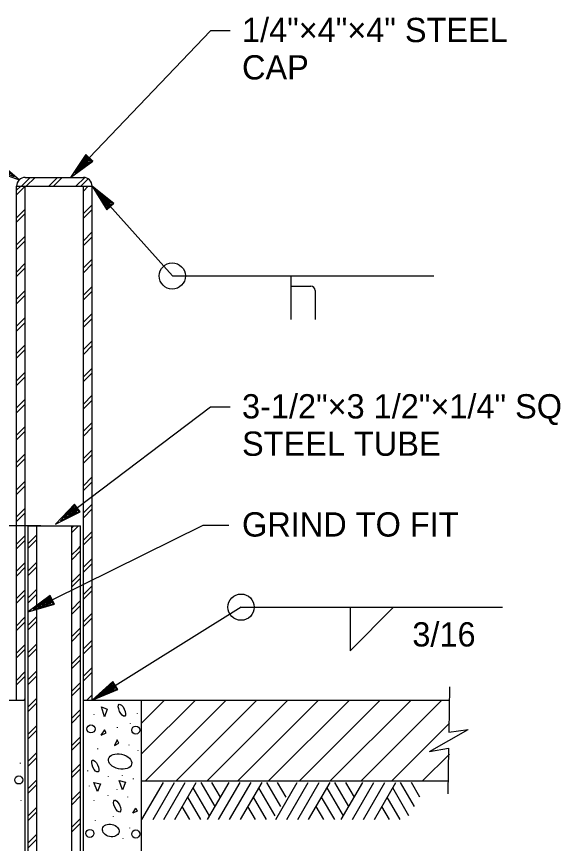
# Model space of a CAD drawing. Extents: x -119017 to -116080, y -104449 to -102845.
# Drawn here: x -117755.4 to -117621.1, y -103410.1 to -103205.8 of the extents above; entities that cross this region are included whole.
import ezdxf

# ---------------------------------------------------------------- set-up
doc = ezdxf.new("R2010")
doc.units = 0
for name, color, linetype in [('C-DETL-MEDM', 7, 'Continuous'), ('C-DIMS', 7, 'Continuous'), ('C-MARK', 7, 'Continuous'), ('C-PATT', 7, 'Continuous'), ('C-TEXT', 7, 'Continuous'), ('Misc CnstDet(22)', 7, 'Continuous')]:
    doc.layers.add(name, color=color, linetype=linetype)

msp = doc.modelspace()

# ---------------------------------------------------------------- linework, layer by layer
at = {"layer": 'C-DETL-MEDM'}
for p, q in [((-117753.26, -103245.52), (-117738.92, -103245.52)), ((-117755.42, -103247.67), (-117736.76, -103247.67)), ((-117755.42, -103374.64), (-117755.42, -103247.67)), ((-117753.26, -103374.64), (-117753.26, -103247.67)), ((-117738.92, -103374.64), (-117738.92, -103247.67)), ((-117736.76, -103374.64), (-117736.76, -103247.67)), ((-117752.59, -103482.24), (-117752.59, -103331.6)), ((-117752.59, -103331.6), (-117739.59, -103331.6)), ((-117750.44, -103482.2), (-117750.44, -103331.6)), ((-117741.74, -103482.2), (-117741.74, -103331.6)), ((-117739.59, -103482.24), (-117739.59, -103331.6)), ((-117828.02, -103374.64), (-117753.26, -103374.64)), ((-117753.26, -103503.76), (-117753.26, -103374.64)), ((-117738.92, -103503.76), (-117738.92, -103374.64)), ((-117738.92, -103374.64), (-117648.54, -103374.64)), ((-117724.57, -103503.76), (-117724.57, -103374.64)), ((-117724.57, -103394.59), (-117648.86, -103394.59))]:
    msp.add_line(p, q, dxfattribs=at)
for centre, start, end in [((-117753.26, -103247.67), 90, 180), ((-117738.92, -103247.67), 0, 90)]:
    msp.add_arc(centre, 2.15, start, end, dxfattribs=at)
at = {"layer": 'C-DIMS'}
msp.add_line((-117749.45, -103331.6), (-117793.52, -103331.6), dxfattribs=at)
at = {"layer": 'C-MARK'}
for p, q in [((-117716.94, -103269.86), (-117652.38, -103269.86)), ((-117699.96, -103351.69), (-117635.4, -103351.69)), ((-117673.06, -103351.69), (-117673.06, -103362.45)), ((-117673.06, -103362.45), (-117662.3, -103351.69)), ((-117648.49, -103371.41), (-117648.67, -103382.57)), ((-117653.48, -103387.33), (-117643.92, -103381.94)), ((-117648.67, -103382.57), (-117643.92, -103381.94)), ((-117648.67, -103382.57), (-117648.67, -103382.57)), ((-117653.48, -103387.33), (-117648.73, -103386.55)), ((-117648.73, -103386.55), (-117648.91, -103397.81)), ((-117648.73, -103386.55), (-117648.73, -103386.55))]:
    msp.add_line(p, q, dxfattribs=at)
for points in [[(-117702.65, -103209.33), (-117707.49, -103209.33), (-117737.45, -103240.66)], [(-117716.94, -103269.86), (-117736.76, -103247.67)], [(-117702.65, -103302.31), (-117707.49, -103302.31), (-117740.4, -103327.17)], [(-117702.97, -103331.49), (-117709.43, -103331.49), (-117746.57, -103349.88)], [(-117699.96, -103351.69), (-117736.76, -103374.64)]]:
    msp.add_lwpolyline(points, dxfattribs=at)
for centre in [(-117716.96, -103269.87), (-117699.97, -103351.7)]:
    msp.add_ellipse(centre, major_axis=(0, 3.24), ratio=0.999972, dxfattribs=at)
at = {"layer": 'C-PATT'}
for p, q in [((-117754.2, -103247.67), (-117752.04, -103245.52)), ((-117753.01, -103247.67), (-117750.86, -103245.52)), ((-117747.47, -103247.67), (-117745.32, -103245.52)), ((-117746.29, -103247.67), (-117744.13, -103245.52)), ((-117740.74, -103247.67), (-117738.59, -103245.52)), ((-117739.56, -103247.67), (-117737.75, -103245.86)), ((-117755.42, -103248.68), (-117754.4, -103247.67)), ((-117755.42, -103249.87), (-117753.26, -103247.72)), ((-117738.92, -103248.89), (-117737.7, -103247.67)), ((-117738.92, -103247.71), (-117738.88, -103247.67)), ((-117755.42, -103255.5), (-117753.26, -103253.35)), ((-117738.92, -103254.43), (-117736.76, -103252.28)), ((-117738.92, -103255.62), (-117736.76, -103253.46)), ((-117755.42, -103256.59), (-117753.26, -103254.44)), ((-117738.92, -103261.16), (-117736.76, -103259.01)), ((-117755.42, -103262.18), (-117753.26, -103260.03)), ((-117755.42, -103263.32), (-117753.26, -103261.17)), ((-117738.92, -103262.34), (-117736.76, -103260.19)), ((-117738.92, -103267.88), (-117736.76, -103265.73)), ((-117755.42, -103268.9), (-117753.26, -103266.75)), ((-117738.92, -103269.07), (-117736.76, -103266.91)), ((-117755.42, -103270.04), (-117753.26, -103267.89)), ((-117755.42, -103275.58), (-117753.26, -103273.43)), ((-117738.92, -103274.64), (-117736.76, -103272.49)), ((-117738.92, -103275.79), (-117736.76, -103273.64)), ((-117755.42, -103276.77), (-117753.26, -103274.62)), ((-117738.92, -103281.33), (-117736.76, -103279.18)), ((-117755.42, -103282.31), (-117753.26, -103280.16)), ((-117755.42, -103283.49), (-117753.26, -103281.34)), ((-117738.92, -103282.52), (-117736.76, -103280.36)), ((-117738.92, -103288.06), (-117736.76, -103285.9)), ((-117755.42, -103289.03), (-117753.26, -103286.88)), ((-117755.42, -103290.22), (-117753.26, -103288.07)), ((-117738.92, -103289.24), (-117736.76, -103287.09)), ((-117755.42, -103295.76), (-117753.26, -103293.61)), ((-117738.92, -103294.78), (-117736.76, -103292.63)), ((-117738.92, -103295.97), (-117736.76, -103293.81)), ((-117755.42, -103296.94), (-117753.26, -103294.79)), ((-117755.42, -103302.48), (-117753.26, -103300.33)), ((-117738.92, -103301.51), (-117736.76, -103299.35)), ((-117738.92, -103302.69), (-117736.76, -103300.54)), ((-117755.42, -103303.67), (-117753.26, -103301.51)), ((-117738.92, -103308.23), (-117736.76, -103306.08)), ((-117755.42, -103309.21), (-117753.26, -103307.06)), ((-117755.42, -103310.39), (-117753.26, -103308.24)), ((-117738.92, -103309.42), (-117736.76, -103307.26)), ((-117755.42, -103315.93), (-117753.26, -103313.78)), ((-117738.92, -103314.99), (-117736.76, -103312.84)), ((-117738.92, -103316.14), (-117736.76, -103313.99)), ((-117755.42, -103317.12), (-117753.26, -103314.96)), ((-117755.42, -103322.71), (-117753.26, -103320.56)), ((-117738.92, -103321.69), (-117736.76, -103319.54)), ((-117738.92, -103322.87), (-117736.76, -103320.71)), ((-117755.42, -103323.84), (-117753.26, -103321.69)), ((-117738.92, -103328.41), (-117736.76, -103326.25)), ((-117755.42, -103329.38), (-117753.26, -103327.23)), ((-117755.42, -103330.57), (-117753.26, -103328.41)), ((-117738.92, -103329.59), (-117736.76, -103327.44)), ((-117741.74, -103333.25), (-117740.09, -103331.6)), ((-117741.74, -103332.07), (-117741.27, -103331.6)), ((-117738.92, -103335.13), (-117736.76, -103332.98)), ((-117755.42, -103336.11), (-117753.26, -103333.96)), ((-117755.42, -103337.29), (-117753.26, -103335.14)), ((-117752.59, -103335.98), (-117750.44, -103333.83)), ((-117752.59, -103337.16), (-117750.44, -103335.01)), ((-117738.92, -103336.31), (-117736.76, -103334.16)), ((-117741.74, -103338.79), (-117740.23, -103337.28)), ((-117740.23, -103337.28), (-117739.59, -103336.64)), ((-117741.74, -103339.97), (-117739.59, -103337.82)), ((-117755.42, -103342.83), (-117753.26, -103340.68)), ((-117752.59, -103342.7), (-117750.44, -103340.55)), ((-117738.92, -103341.86), (-117736.76, -103339.7)), ((-117738.92, -103343.04), (-117736.76, -103340.89)), ((-117755.42, -103344.02), (-117753.26, -103341.86)), ((-117752.59, -103343.88), (-117750.44, -103341.73)), ((-117741.74, -103345.52), (-117739.59, -103343.36)), ((-117741.74, -103346.7), (-117739.59, -103344.55)), ((-117755.42, -103349.56), (-117753.26, -103347.41)), ((-117752.59, -103349.43), (-117750.44, -103347.28)), ((-117738.92, -103348.58), (-117736.76, -103346.43)), ((-117755.42, -103350.74), (-117753.26, -103348.59)), ((-117752.59, -103350.61), (-117750.44, -103348.46)), ((-117738.92, -103349.76), (-117736.76, -103347.61)), ((-117741.74, -103352.24), (-117739.59, -103350.09)), ((-117741.74, -103353.42), (-117739.59, -103351.27)), ((-117738.92, -103355.31), (-117736.76, -103353.15)), ((-117755.42, -103356.28), (-117753.26, -103354.13)), ((-117755.42, -103357.47), (-117753.26, -103355.31)), ((-117752.59, -103356.18), (-117750.44, -103354.03)), ((-117752.59, -103357.33), (-117750.44, -103355.18)), ((-117738.92, -103356.49), (-117736.76, -103354.34)), ((-117741.74, -103358.97), (-117739.59, -103356.81)), ((-117741.74, -103360.15), (-117739.59, -103358)), ((-117755.42, -103363.1), (-117753.26, -103360.95)), ((-117752.59, -103362.88), (-117750.44, -103360.73)), ((-117738.92, -103362.03), (-117736.76, -103359.88)), ((-117738.92, -103363.21), (-117736.76, -103361.06)), ((-117755.42, -103364.19), (-117753.26, -103362.04)), ((-117752.59, -103364.06), (-117750.44, -103361.91)), ((-117741.74, -103365.69), (-117739.59, -103363.54)), ((-117741.74, -103366.87), (-117739.59, -103364.72)), ((-117755.42, -103369.78), (-117753.26, -103367.63)), ((-117752.59, -103369.6), (-117750.44, -103367.45)), ((-117738.92, -103368.76), (-117736.76, -103366.6)), ((-117738.92, -103369.94), (-117736.76, -103367.79)), ((-117755.42, -103370.92), (-117753.26, -103368.76)), ((-117752.59, -103370.78), (-117750.44, -103368.63)), ((-117741.74, -103372.44), (-117739.59, -103370.29)), ((-117741.74, -103373.6), (-117739.59, -103371.45)), ((-117738.07, -103374.64), (-117736.76, -103373.33)), ((-117753.55, -103374.64), (-117753.26, -103374.35)), ((-117752.59, -103376.33), (-117750.44, -103374.18)), ((-117752.59, -103377.51), (-117750.44, -103375.36)), ((-117736.89, -103374.64), (-117736.76, -103374.51)), ((-117724.57, -103380.34), (-117718.87, -103374.64)), ((-117724.57, -103387.95), (-117711.26, -103374.64)), ((-117723.6, -103394.59), (-117703.65, -103374.64)), ((-117715.99, -103394.59), (-117696.04, -103374.64)), ((-117708.38, -103394.59), (-117688.43, -103374.64)), ((-117700.78, -103394.59), (-117680.83, -103374.64)), ((-117693.17, -103394.59), (-117673.22, -103374.64)), ((-117685.56, -103394.59), (-117665.61, -103374.64)), ((-117677.95, -103394.59), (-117658, -103374.64)), ((-117670.34, -103394.59), (-117650.39, -103374.64)), ((-117741.74, -103379.14), (-117739.59, -103376.99)), ((-117741.74, -103380.32), (-117739.59, -103378.17)), ((-117736.24, -103378.31), (-117736.24, -103378.2)), ((-117725.54, -103377.98), (-117725.54, -103377.88)), ((-117752.59, -103383.05), (-117750.44, -103380.9)), ((-117752.59, -103384.23), (-117750.44, -103382.08)), ((-117730.49, -103381.48), (-117730.49, -103381.37)), ((-117727.31, -103380.46), (-117727.31, -103380.35)), ((-117662.73, -103394.59), (-117648.54, -103380.39)), ((-117741.74, -103385.87), (-117739.59, -103383.71)), ((-117741.74, -103387.05), (-117739.59, -103384.9)), ((-117727.58, -103385.78), (-117727.58, -103385.68)), ((-117752.59, -103389.78), (-117750.44, -103387.63)), ((-117735.33, -103386.75), (-117735.33, -103386.65)), ((-117725.38, -103387.18), (-117725.38, -103387.08)), ((-117655.13, -103394.59), (-117648.54, -103388)), ((-117754.44, -103390.29), (-117754.44, -103390.18)), ((-117752.59, -103390.96), (-117750.44, -103388.81)), ((-117741.74, -103392.59), (-117739.59, -103390.44)), ((-117741.74, -103393.77), (-117739.59, -103391.62)), ((-117737.8, -103392.19), (-117737.8, -103392.08)), ((-117752.59, -103396.5), (-117750.44, -103394.35)), ((-117732.75, -103393.64), (-117732.75, -103393.53)), ((-117729.25, -103393.37), (-117729.25, -103393.26)), ((-117726.56, -103394.18), (-117726.56, -103394.07)), ((-117752.59, -103397.68), (-117750.44, -103395.53)), ((-117737.43, -103395.95), (-117737.43, -103395.85)), ((-117724.44, -103404.2), (-117719.12, -103394.98)), ((-117721.72, -103404.2), (-117716.44, -103395)), ((-117719.02, -103404.16), (-117713.77, -103395.03)), ((-117716.35, -103404.16), (-117711.04, -103395.03)), ((-117707.74, -103403.27), (-117711.77, -103396.3)), ((-117706.38, -103400.94), (-117709.85, -103395)), ((-117708.27, -103404.2), (-117702.93, -103394.98)), ((-117705.05, -103398.63), (-117707.17, -103394.98)), ((-117705.53, -103404.2), (-117700.21, -103394.98)), ((-117702.81, -103404.2), (-117697.5, -103394.98)), ((-117700.1, -103404.2), (-117694.78, -103394.98)), ((-117691.56, -103403.27), (-117695.57, -103396.3)), ((-117690.19, -103400.94), (-117693.63, -103395)), ((-117691.4, -103404.2), (-117686.08, -103394.98)), ((-117688.86, -103398.63), (-117690.96, -103394.98)), ((-117688.67, -103404.2), (-117683.39, -103395)), ((-117685.97, -103404.16), (-117680.72, -103395.03)), ((-117683.3, -103404.16), (-117678, -103395.03)), ((-117674.69, -103403.27), (-117678.73, -103396.3)), ((-117673.34, -103400.94), (-117676.81, -103395)), ((-117675.22, -103404.2), (-117669.89, -103394.98)), ((-117672, -103398.63), (-117674.12, -103394.98)), ((-117672.48, -103404.2), (-117667.16, -103394.98)), ((-117669.76, -103404.2), (-117664.46, -103394.98)), ((-117667.06, -103404.2), (-117661.74, -103394.98)), ((-117658.52, -103403.27), (-117662.52, -103396.3)), ((-117657.15, -103400.94), (-117660.58, -103395)), ((-117655.81, -103398.63), (-117657.91, -103394.98)), ((-117741.74, -103399.31), (-117739.59, -103397.16)), ((-117741.74, -103400.5), (-117739.59, -103398.34)), ((-117732.8, -103398.27), (-117732.8, -103398.16)), ((-117730.54, -103396.76), (-117730.54, -103396.65)), ((-117727.9, -103398.64), (-117727.9, -103398.54)), ((-117709.91, -103404.16), (-117713.13, -103398.63)), ((-117693.7, -103404.16), (-117696.92, -103398.63)), ((-117676.86, -103404.16), (-117680.08, -103398.63)), ((-117660.65, -103404.16), (-117663.87, -103398.63)), ((-117754.27, -103399.49), (-117754.27, -103399.38)), ((-117736.24, -103399.56), (-117736.24, -103399.45)), ((-117752.59, -103403.23), (-117750.44, -103401.08)), ((-117752.59, -103404.41), (-117750.44, -103402.26)), ((-117712.61, -103404.2), (-117714.5, -103400.98)), ((-117696.4, -103404.2), (-117698.29, -103400.98)), ((-117679.56, -103404.2), (-117681.45, -103400.98)), ((-117663.36, -103404.2), (-117665.24, -103400.98)), ((-117741.74, -103406.04), (-117739.59, -103403.89)), ((-117735.92, -103404.4), (-117735.92, -103404.29)), ((-117731.46, -103403.49), (-117731.46, -103403.38)), ((-117741.74, -103407.22), (-117739.59, -103405.07)), ((-117727.47, -103406.28), (-117727.47, -103406.18)), ((-117724.73, -103404.78), (-117724.57, -103404.78)), ((-117752.59, -103409.95), (-117750.44, -103407.8)), ((-117729.09, -103408.87), (-117729.09, -103408.76)), ((-117752.59, -103411.13), (-117750.44, -103408.98))]:
    msp.add_line(p, q, dxfattribs=at)
for points in [[(-117733.71, -103378.79), (-117734.47, -103376.32), (-117733.02, -103376.91), (-117733.71, -103378.79)], [(-117734.52, -103383.31), (-117733.28, -103382.77), (-117733.71, -103381.97), (-117734.58, -103383.31)], [(-117731.19, -103385.84), (-117730.16, -103385.3), (-117730.54, -103384.49), (-117731.24, -103385.89)], [(-117729.25, -103396.87), (-117730.06, -103394.5), (-117728.5, -103394.93), (-117729.25, -103396.81)], [(-117735.44, -103397.24), (-117736.3, -103395.04), (-117734.68, -103395.36), (-117735.44, -103397.24)], [(-117726.72, -103402.62), (-117725.97, -103401.33), (-117725.64, -103402.14), (-117726.72, -103402.62)]]:
    msp.add_lwpolyline(points, dxfattribs=at)
for centre in [(-117737.04, -103381.78), (-117725.97, -103382.08), (-117754.87, -103394.39), (-117737.31, -103407.6), (-117725.97, -103407.75)]:
    msp.add_circle(centre, 0.997, dxfattribs=at)
for centre, major_axis, ratio in [((-117729.39, -103377.17), (0.69, -1.47), 0.393469), ((-117729.86, -103389.83), (-2.85, 0.63), 0.634119), ((-117735.97, -103390.95), (0.69, -1.47), 0.393469), ((-117730.57, -103400.84), (0.69, -1.47), 0.393469), ((-117732.15, -103406.87), (2.04, -0.42), 0.736889)]:
    msp.add_ellipse(centre, major_axis=major_axis, ratio=ratio, dxfattribs=at)
at = {"layer": 'C-TEXT'}
msp.add_line((-117687.67, -103269.86), (-117687.67, -103280.62), dxfattribs=at)
for points in [[(-117736.59, -103241.48), (-117738.3, -103239.84), (-117742.1, -103245.52), (-117736.59, -103241.48), (-117737.67, -103240.89), (-117738.22, -103240.22), (-117741.05, -103244.51), (-117736.9, -103241.48), (-117737.82, -103241.05), (-117738.21, -103240.68), (-117740.2, -103243.61), (-117737.43, -103241.57), (-117738.21, -103240.9), (-117739.38, -103242.68), (-117737.81, -103241.5), (-117738.27, -103241.29), (-117738.64, -103241.9), (-117737.45, -103240.66)], [(-117759.99, -103241.74), (-117761.16, -103243.79), (-117754.74, -103246.1), (-117759.99, -103241.74), (-117760.29, -103242.92), (-117760.82, -103243.62), (-117755.97, -103245.33), (-117759.91, -103242.03), (-117760.11, -103243.03), (-117760.37, -103243.5), (-117757.05, -103244.72), (-117759.69, -103242.52), (-117760.15, -103243.44), (-117758.15, -103244.15), (-117759.67, -103242.91), (-117759.77, -103243.41), (-117759.08, -103243.62), (-117760.57, -103242.76)], [(-117733.13, -103253.51), (-117731.37, -103251.94), (-117736.76, -103247.67), (-117733.13, -103253.51), (-117732.47, -103252.49), (-117731.75, -103251.99), (-117735.8, -103248.83), (-117733.12, -103253.21), (-117732.61, -103252.32), (-117732.21, -103251.97), (-117734.98, -103249.75), (-117733.16, -103252.67), (-117732.43, -103251.95), (-117734.11, -103250.64), (-117733.06, -103252.3), (-117732.81, -103251.86), (-117733.4, -103251.44), (-117732.25, -103252.72)], [(-117687.65, -103272.36), (-117682.77, -103272.36)], [(-117681.65, -103273.48), (-117681.65, -103280.62)], [(-117739.68, -103328.11), (-117741.11, -103326.22), (-117745.76, -103331.22), (-117739.68, -103328.11), (-117740.65, -103327.36), (-117741.09, -103326.61), (-117744.57, -103330.39), (-117739.98, -103328.07), (-117740.83, -103327.49), (-117741.15, -103327.06), (-117743.58, -103329.64), (-117740.52, -103328.07), (-117741.18, -103327.29), (-117742.63, -103328.85), (-117740.89, -103327.94), (-117741.31, -103327.65), (-117741.77, -103328.2), (-117740.4, -103327.17)], [(-117746.04, -103350.94), (-117747.09, -103348.82), (-117752.59, -103352.86), (-117746.04, -103350.94), (-117746.86, -103350.02), (-117747.14, -103349.2), (-117751.27, -103352.26), (-117746.33, -103350.84), (-117747.05, -103350.11), (-117747.29, -103349.63), (-117750.16, -103351.71), (-117746.86, -103350.74), (-117747.36, -103349.85), (-117749.07, -103351.12), (-117747.19, -103350.55), (-117747.55, -103350.18), (-117748.11, -103350.64), (-117746.57, -103349.88)], [(-117730.39, -103372.06), (-117731.64, -103370.05), (-117736.76, -103374.64), (-117730.39, -103372.06), (-117731.29, -103371.22), (-117731.65, -103370.43), (-117735.46, -103373.89), (-117730.68, -103371.99), (-117731.47, -103371.34), (-117731.75, -103370.88), (-117734.41, -103373.23), (-117731.22, -103371.94), (-117731.81, -103371.1), (-117733.39, -103372.53), (-117731.57, -103371.78), (-117731.97, -103371.45), (-117732.47, -103371.96), (-117731.01, -103371.05)]]:
    msp.add_lwpolyline(points, dxfattribs=at)
msp.add_arc((-117682.77, -103273.48), 1.12, 0, 90, dxfattribs=at)

# ---------------------------------------------------------------- texts
at = {"layer": 'Misc CnstDet(22)'}
for s, p in [('1/4"×4"×4" STEEL', (-117699.74, -103212.1)), ('CAP', (-117699.74, -103221.33)), ('3-1/2"×3 1/2"×1/4" SQ', (-117699.74, -103305.08)), ('STEEL TUBE', (-117699.74, -103314.31)), ('GRIND TO FIT', (-117699.74, -103334.26)), ('3/16', (-117657.68, -103361.42))]:
    msp.add_text(s, height=6, dxfattribs=at).set_placement(p)

doc.saveas('drawing.dxf')
